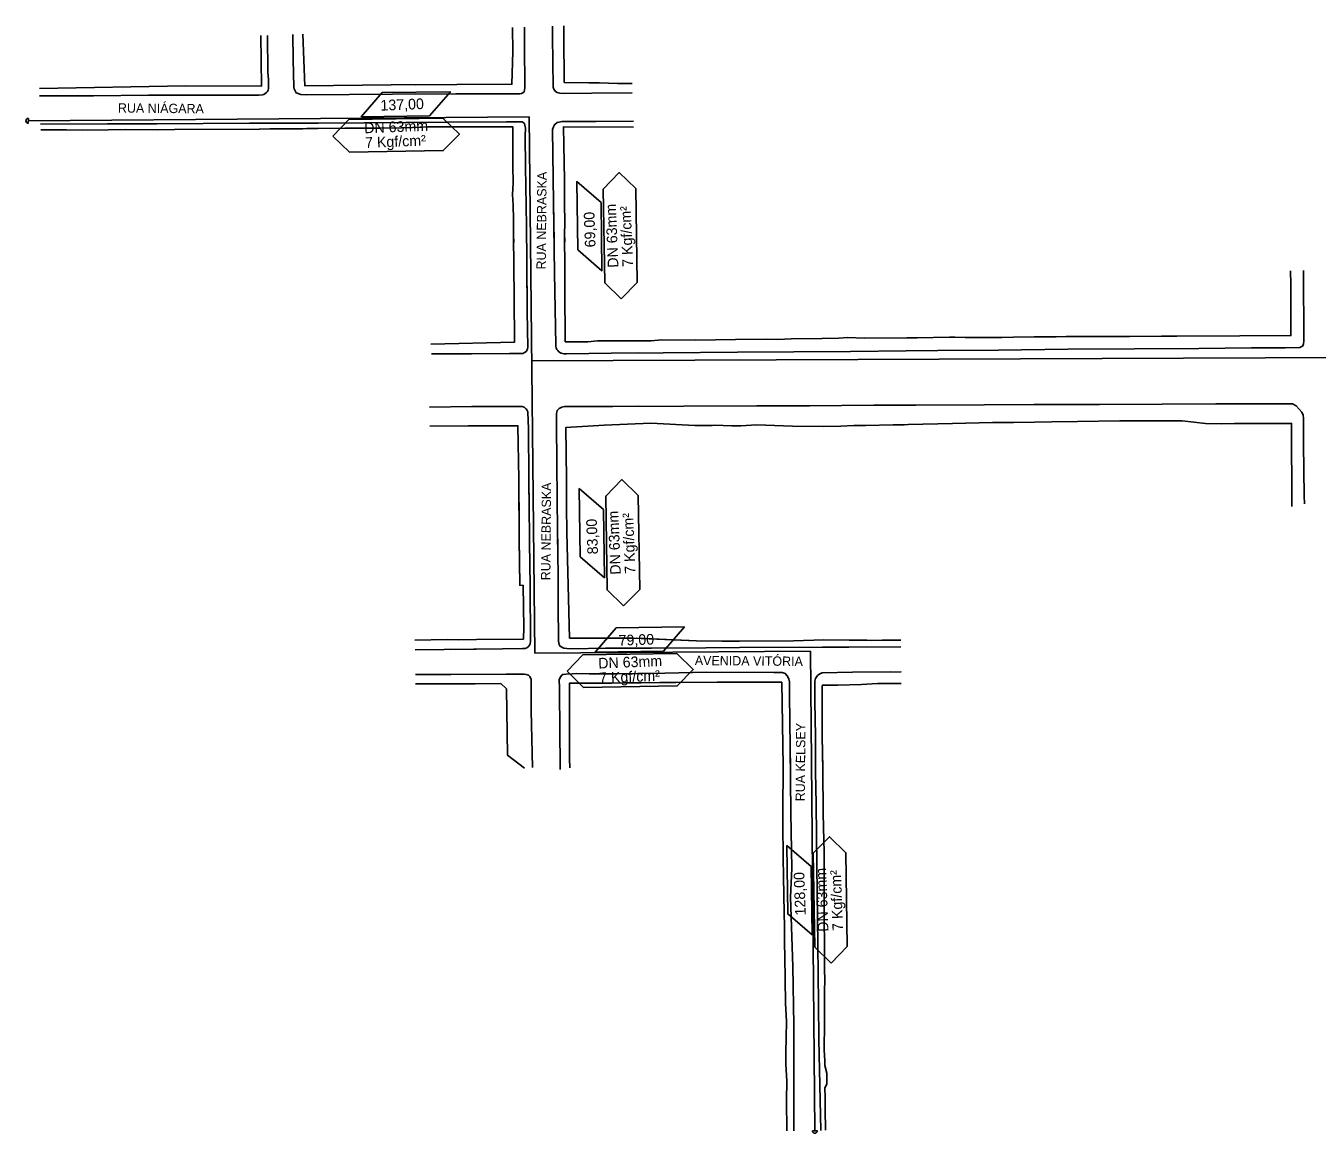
# Model space of a CAD drawing. Extents: x 325899 to 364828, y 7568995 to 7592502.
# Drawn here: x 353880 to 355157, y 7574104 to 7575200 of the extents above; entities that cross this region are included whole.
import ezdxf

# ---------------------------------------------------------------- set-up
doc = ezdxf.new("R2010")
doc.units = 0
for name, color, linetype in [('CERCA_ARAME', 7, 'Continuous'), ('MEIO_FIO_GUIA', 7, 'Continuous'), ('MURO_DIVISA', 7, 'Continuous'), ('SIMBOLO', 7, 'Continuous'), ('TEXTO', 7, 'Continuous'), ('TUBO_PEAD_GN_63', 7, 'Continuous')]:
    doc.layers.add(name, color=color, linetype=linetype)

msp = doc.modelspace()

# ---------------------------------------------------------------- linework, layer by layer
at = {"layer": 'CERCA_ARAME'}
msp.add_line((354480.9, 7574594.1), (354417.9, 7574593.9), dxfattribs=at)
at = {"layer": 'MEIO_FIO_GUIA'}
for points in [[(354144.2, 7575191), (354144.7, 7575166.4), (354145.3, 7575138.9), (354145.6, 7575137.3), (354146.4, 7575136), (354147.6, 7575133.5), (354152.1, 7575131.8), (354157.6, 7575131.5), (354243, 7575131.9), (354305.6, 7575132.2), (354368.8, 7575132.4), (354370.5, 7575132.6), (354371.9, 7575133.3), (354373.1, 7575134.5), (354373.5, 7575136.2), (354373.9, 7575138.2), (354373.5, 7575181.2), (354373.3, 7575198.4)], [(354265.3, 7575132), (354305.6, 7575132.2), (354368.8, 7575132.4), (354370.5, 7575132.6), (354371.9, 7575133.3), (354373.1, 7575134.5), (354373.5, 7575136.2), (354373.9, 7575138.2), (354373.5, 7575181.2), (354373.3, 7575198.4)], [(354401.1, 7575199.3), (354401.2, 7575188.9), (354401.9, 7575139), (354402.4, 7575137), (354404, 7575134.8), (354405.7, 7575133.7), (354408.3, 7575133), (354411.9, 7575132.8), (354440.1, 7575133), (354480.1, 7575133.3)], [(354401.1, 7575199.3), (354401.2, 7575188.9), (354401.9, 7575139), (354402.4, 7575137), (354404, 7575134.8), (354405.7, 7575133.7), (354408.3, 7575133), (354411.9, 7575132.8), (354440.1, 7575133), (354480.1, 7575133.3)], [(353893.9, 7575130.3), (353947.2, 7575130.3), (354001.6, 7575130.9), (354056, 7575131.1), (354102.9, 7575131.2), (354110.7, 7575131.2), (354114.3, 7575131.3), (354115.6, 7575131.8), (354117.1, 7575132.6), (354118.3, 7575133.7), (354119.2, 7575134.8), (354119.8, 7575136.1), (354120.1, 7575137.8), (354120.2, 7575139.2), (354120.1, 7575146.7), (354119.6, 7575153.7), (354119.4, 7575190.2)], [(353894.8, 7575102.4), (353961.1, 7575102.6), (354009.8, 7575102.8), (354101.4, 7575103.3), (354109, 7575103.4), (354169.8, 7575103.5), (354214.9, 7575103.7), (354296.9, 7575104.2), (354355.6, 7575104.6), (354363.5, 7575104.7), (354369.4, 7575104.8), (354371.1, 7575104.6), (354372.3, 7575104.1), (354373.4, 7575103), (354373.9, 7575101.4), (354374.3, 7575098.4), (354374.2, 7575090.7), (354374.6, 7575060.3), (354375.1, 7575022), (354375.3, 7575000.7), (354375.4, 7574985.5)], [(354265.6, 7575104), (354296.9, 7575104.2), (354355.6, 7575104.6), (354363.5, 7575104.7), (354369.4, 7575104.8), (354371.1, 7575104.6), (354372.3, 7575104.1), (354373.4, 7575103), (354373.9, 7575101.4), (354374.3, 7575098.4), (354374.2, 7575090.7), (354374.6, 7575060.3), (354375.1, 7575022), (354375.3, 7575000.7), (354375.6, 7574968.1), (354376.2, 7574916.6), (354376.6, 7574881.9), (354376.4, 7574880.3), (354376, 7574879), (354375.5, 7574878), (354374.2, 7574876.8), (354371.9, 7574875.7), (354369.5, 7574875.4), (354366.7, 7574875.4), (354358.7, 7574875.5), (354321, 7574875.1), (354281.6, 7574875.2)], [(354481.2, 7575105.2), (354444, 7575105), (354417.3, 7575104.9), (354410.4, 7575105), (354407.7, 7575104.4), (354405.8, 7575103.9), (354403.2, 7575101.8), (354402, 7575099.8), (354401.2, 7575097), (354402.1, 7575024.9), (354402.7, 7574985.9)], [(354481.2, 7575105.2), (354444, 7575105), (354417.3, 7575104.9), (354410.4, 7575105), (354407.7, 7575104.4), (354405.8, 7575103.9), (354403.2, 7575101.8), (354402, 7575099.8), (354401.2, 7575097), (354402.1, 7575024.9), (354403.1, 7574955), (354404.3, 7574884), (354404.5, 7574882.4), (354404.8, 7574881.1), (354405.5, 7574879.6), (354406.4, 7574878.5), (354407.3, 7574877.3), (354409, 7574876.3)], [(354375.6, 7574963.4), (354376.2, 7574916.6), (354376.6, 7574881.9), (354376.4, 7574880.3), (354376, 7574879), (354375.5, 7574878), (354374.2, 7574876.8), (354371.9, 7574875.7), (354369.5, 7574875.4), (354366.7, 7574875.4), (354358.7, 7574875.5), (354321, 7574875.1), (354281.6, 7574875.2)], [(354403, 7574963.6), (354403.1, 7574955), (354404.3, 7574884), (354404.5, 7574882.4), (354404.8, 7574881.1), (354405.5, 7574879.6), (354406.4, 7574878.5), (354407.3, 7574877.3), (354409, 7574876.3)], [(354510.5, 7574876.3), (354584, 7574876.8), (354639.7, 7574877.3), (354696, 7574877.6), (354750.9, 7574878.2), (354782.3, 7574878.5), (354842.4, 7574878.9), (354911, 7574879.8), (354976.4, 7574880.1), (355040.3, 7574880.6), (355092.4, 7574881.1), (355117.7, 7574881.3), (355125.7, 7574881.3), (355140.3, 7574881.5), (355142.3, 7574882.4), (355143.2, 7574883.1), (355144, 7574885.1), (355144.3, 7574887.7), (355144, 7574957.7)], [(354409, 7574876.3), (354409.7, 7574875.9), (354412.5, 7574875.3), (354415, 7574875.1), (354459.2, 7574875.8), (354510.5, 7574876.3)], [(354409, 7574876.3), (354409.7, 7574875.9), (354412.5, 7574875.3), (354415, 7574875.1), (354459.2, 7574875.8), (354485.9, 7574876.1)], [(354405.8, 7574720.6), (354405.7, 7574728.3), (354405.4, 7574770.3), (354405, 7574802.3), (354405, 7574810), (354405.1, 7574816.3), (354405.3, 7574817.5), (354405.8, 7574819.3), (354407.6, 7574821.1), (354410.4, 7574822.6), (354413, 7574823), (354460.8, 7574823.2), (354530.8, 7574823.4), (354603.2, 7574823.9), (354655.2, 7574823.9), (354719, 7574824.4), (354760.6, 7574824.3), (354828, 7574824.6), (354877.3, 7574825.1), (354942.3, 7574825.1), (355004.2, 7574825.4), (355057.1, 7574825.6), (355121.5, 7574825.9), (355129.4, 7574825.9), (355133.1, 7574825.8), (355136.6, 7574823.7), (355139.7, 7574820.6), (355142.3, 7574817.5), (355143.6, 7574814.5), (355144, 7574811.4), (355144.1, 7574785.8), (355144.5, 7574734.7), (355144.8, 7574727)], [(354265.4, 7574582.5), (354351.7, 7574583.4), (354371.6, 7574583.9), (354374, 7574583.9), (354375.7, 7574584.4), (354377.5, 7574585.6), (354378.4, 7574587), (354379.1, 7574588.3), (354379.5, 7574591.1), (354379.1, 7574645.9), (354378.3, 7574688.6), (354378.4, 7574693.9), (354377.7, 7574751.8), (354377.3, 7574801.2), (354377.2, 7574808.9), (354376.9, 7574818), (354376.2, 7574819.2), (354375.3, 7574820.4), (354374.4, 7574821.3), (354373, 7574822.5), (354371, 7574823.2), (354365.8, 7574823.1), (354358, 7574823.1), (354321.4, 7574823), (354279.4, 7574822.6)], [(354378.1, 7574720.4), (354377.7, 7574751.8), (354377.3, 7574801.2), (354377.2, 7574808.9), (354376.9, 7574818), (354376.2, 7574819.2), (354375.3, 7574820.4), (354374.4, 7574821.3), (354373, 7574822.5), (354371, 7574823.2), (354365.8, 7574823.1), (354358, 7574823.1), (354321.4, 7574823), (354279.4, 7574822.6)], [(354488.7, 7574584.1), (354453.6, 7574584), (354419.6, 7574583.6), (354415.3, 7574583.7), (354412.2, 7574584.1), (354409.6, 7574585.4), (354408.5, 7574586.4), (354407.7, 7574587.8), (354407.1, 7574590.9), (354406.8, 7574627.7), (354406.6, 7574652.4), (354406.4, 7574680.8), (354405.7, 7574728.3), (354405.4, 7574770.3), (354405, 7574802.3), (354405, 7574810), (354405.1, 7574816.3), (354405.3, 7574817.5), (354405.8, 7574819.3), (354407.6, 7574821.1), (354410.4, 7574822.6), (354413, 7574823), (354460.8, 7574823.2), (354486.4, 7574823.3)], [(354299.8, 7574582.9), (354351.7, 7574583.4), (354371.6, 7574583.9), (354374, 7574583.9), (354375.7, 7574584.4), (354377.5, 7574585.6), (354378.4, 7574587), (354379.1, 7574588.3), (354379.5, 7574591.1), (354379.1, 7574645.9), (354378.3, 7574688.6), (354378.4, 7574691.6)], [(354694.2, 7574585.2), (354668.3, 7574585.1), (354586.1, 7574584.8), (354552.9, 7574584.5), (354499.1, 7574584.1), (354453.6, 7574584), (354419.6, 7574583.6), (354415.3, 7574583.7), (354412.2, 7574584.1), (354409.6, 7574585.4), (354408.5, 7574586.4), (354407.7, 7574587.8), (354407.1, 7574590.9), (354406.8, 7574627.7), (354406.6, 7574652.4), (354406.4, 7574680.8), (354406.2, 7574691.8)], [(354745.7, 7574585.5), (354668.3, 7574585.1), (354586.1, 7574584.8), (354552.9, 7574584.5), (354499.1, 7574584.1), (354484.8, 7574584.1)], [(354265.6, 7574558.1), (354300.6, 7574558.1), (354355.2, 7574558.5), (354373.1, 7574558.4), (354375.2, 7574558.1), (354377.4, 7574557.5), (354378.8, 7574556.1), (354380, 7574553.1), (354379.9, 7574545.1), (354380.2, 7574522.5), (354380.9, 7574480.1), (354381.3, 7574466)], [(354265.6, 7574558.1), (354300.6, 7574558.1), (354355.2, 7574558.5), (354373.1, 7574558.4), (354375.2, 7574558.1), (354377.4, 7574557.5), (354378.8, 7574556.1), (354380, 7574553.1), (354379.9, 7574545.1), (354380.2, 7574522.5), (354380.9, 7574480.1), (354381.3, 7574466)], [(354408.8, 7574464), (354408.3, 7574506.5), (354408, 7574537.8), (354408, 7574545.3), (354407.8, 7574552.9), (354408.6, 7574555.1), (354410, 7574557.2), (354411.4, 7574558), (354414.4, 7574558.4), (354420.7, 7574558.8), (354424.4, 7574558.9), (354437.5, 7574558.8), (354465.3, 7574558.8), (354512.2, 7574559.4), (354553.5, 7574560.3), (354620, 7574559.9), (354628.4, 7574560), (354631.3, 7574559), (354633.4, 7574556.8), (354634.9, 7574553.7), (354635.7, 7574550.8), (354635.6, 7574538.2)], [(354408.8, 7574464), (354408.3, 7574506.5), (354408, 7574537.8), (354408, 7574545.3), (354407.8, 7574552.9), (354408.6, 7574555.1), (354410, 7574557.2), (354411.4, 7574558), (354414.4, 7574558.4), (354420.7, 7574558.8), (354424.4, 7574558.9), (354437.5, 7574558.8), (354465.3, 7574558.8), (354488.9, 7574559.1)], [(354485.4, 7574559), (354512.2, 7574559.4), (354553.5, 7574560.3), (354620, 7574559.9), (354628.4, 7574560), (354631.3, 7574559), (354633.4, 7574556.8), (354634.9, 7574553.7), (354635.7, 7574550.8), (354635.6, 7574538.2)], [(354745.9, 7574560.7), (354745.9, 7574560.7), (354698, 7574560.2), (354668, 7574559.6), (354665.7, 7574558.8), (354663.4, 7574556.9), (354661.4, 7574554.2), (354660.7, 7574551.6), (354660.6, 7574537.8), (354660.6, 7574530.9), (354661.2, 7574497.4), (354661.4, 7574462.2), (354661.9, 7574429.9), (354662.7, 7574368.8), (354663.5, 7574290.6), (354664.1, 7574232.8), (354664.5, 7574197.2), (354666.7, 7574107.1)], [(354735.7, 7574560.6), (354735.7, 7574560.6), (354698, 7574560.2), (354668, 7574559.6), (354665.7, 7574558.8), (354663.4, 7574556.9), (354661.4, 7574554.2), (354660.7, 7574551.6), (354660.6, 7574537.8), (354660.6, 7574530.9), (354661.2, 7574497.4), (354661.4, 7574465.1)], [(354635.6, 7574538.1), (354636.2, 7574486.3), (354636.4, 7574465)], [(354635.6, 7574538.1), (354636.2, 7574486.3), (354636.9, 7574421.1), (354637.9, 7574366.1), (354636.6, 7574337.9), (354638.8, 7574269.3), (354639.8, 7574211.1), (354639.8, 7574121.2), (354640, 7574106.8)]]:
    msp.add_lwpolyline(points, dxfattribs=at)
at = {"layer": 'MURO_DIVISA'}
for p, q in [((354452.3, 7574804.8), (354498.5, 7574806.5)), ((354480.9, 7574594.1), (354417.9, 7574593.9))]:
    msp.add_line(p, q, dxfattribs=at)
for points in [[(354154.2, 7575191.3), (354156.1, 7575140.4), (354241.5, 7575141.3), (354306.5, 7575141.6), (354361, 7575141.8), (354361.8, 7575174.1), (354361.6, 7575198)], [(354265.2, 7575141.4), (354306.5, 7575141.6), (354361, 7575141.8), (354361.8, 7575174.1), (354361.6, 7575198)], [(354412.2, 7575199.6), (354412.3, 7575190.1), (354412.8, 7575143.6), (354437, 7575143.2), (354447.7, 7575143.3), (354465.6, 7575142.7), (354477.4, 7575142.7)], [(354412.2, 7575199.6), (354412.3, 7575190.1), (354412.8, 7575143.6), (354437, 7575143.2), (354447.7, 7575143.3), (354465.6, 7575142.7), (354479.8, 7575142.7)], [(353893.7, 7575137.6), (354038.6, 7575140.3), (354113.2, 7575139.8), (354112.8, 7575190)], [(353895, 7575096.7), (353920.6, 7575096.6), (353936, 7575096.5), (353962, 7575096.8), (353978.9, 7575097), (354010.6, 7575096.9), (354027.2, 7575097.1), (354111.1, 7575097.3), (354111.1, 7575097.3), (354111.1, 7575097.3)], [(354111.1, 7575097.3), (354111.1, 7575097.3), (354121.7, 7575097.6), (354154.2, 7575097.8), (354158.2, 7575098), (354169.2, 7575098.1), (354195.7, 7575098.3), (354219.8, 7575098.5), (354231.1, 7575098.5), (354251.8, 7575098.8), (354262.8, 7575099.1), (354277.4, 7575099.6), (354287.9, 7575099.8), (354362, 7575099.6), (354361.9, 7575069.3), (354361.9, 7575061.1), (354362.1, 7575044), (354361.7, 7575032.9), (354362.3, 7575022.3), (354362.4, 7575017.8), (354362.6, 7575012.5), (354362.7, 7575002.8), (354362.7, 7574992.1), (354362.8, 7574985.4)], [(354265.6, 7575099.2), (354277.4, 7575099.6), (354287.9, 7575099.8), (354362, 7575099.6), (354361.9, 7575069.3), (354361.9, 7575061.1), (354362.1, 7575044), (354361.7, 7575032.9), (354362.3, 7575022.3), (354362.4, 7575017.8), (354362.6, 7575012.5), (354362.7, 7575002.8), (354362.7, 7574992.1), (354363.2, 7574931.1), (354363.2, 7574931.1)], [(354481.2, 7575099.3), (354412, 7575099.6), (354412.4, 7575082), (354412.9, 7575047), (354413.1, 7575036.3), (354413, 7575020.5), (354413.2, 7575008.4), (354413.2, 7575003.6), (354413.1, 7574994.6), (354413.2, 7574986)], [(354481.2, 7575099.3), (354412, 7575099.6), (354412.4, 7575082), (354412.9, 7575047), (354413.1, 7575036.3), (354413, 7575020.5), (354413.2, 7575008.4), (354413.2, 7575003.6), (354413.1, 7574994.6), (354413.3, 7574957.8), (354413.5, 7574944.3), (354413.5, 7574939.6), (354413.7, 7574887.2), (354436.1, 7574887), (354445.5, 7574887.9), (354485.8, 7574888.1)], [(354413.3, 7574963.6), (354413.3, 7574957.8), (354413.5, 7574944.3), (354413.5, 7574939.6), (354413.7, 7574887.2), (354436.1, 7574887), (354445.5, 7574887.9), (354498.9, 7574888.2), (354508.8, 7574888.9), (354542.6, 7574888.8), (354582.1, 7574889.5), (354612.9, 7574889.7), (354624, 7574889.5), (354637.3, 7574889.9), (354667.7, 7574890.4), (354684.2, 7574890.7), (354693.4, 7574891.5), (354709.5, 7574890.8), (354751.6, 7574891), (354761.9, 7574891.1), (354793.7, 7574891.7), (354799, 7574891.7), (354809.4, 7574891.4), (354821.9, 7574891.4), (354832.4, 7574891.3), (354835.2, 7574891.4), (354845.5, 7574891.5), (354857.2, 7574891.8), (354877.5, 7574892), (354899.3, 7574892.1), (354909.3, 7574892.3), (354920.1, 7574892.4), (354930.4, 7574892.2), (354962.1, 7574892.2), (354971.8, 7574892.2), (355003.5, 7574892.7), (355018.8, 7574892.6), (355080.9, 7574893), (355131.5, 7574893.3), (355131.6, 7574943.7), (355131.2, 7574957.3)], [(354280.7, 7574884.8), (354363.7, 7574886.9), (354363.2, 7574931.1)], [(354265.1, 7574591.9), (354296.8, 7574592.6), (354308.1, 7574592.4), (354325.9, 7574592.6), (354372.4, 7574592.9), (354372.6, 7574593.2), (354372.7, 7574604.3), (354372.3, 7574646.1), (354368.8, 7574646.4), (354368.2, 7574693), (354368.2, 7574705.9), (354367.7, 7574751.2), (354367, 7574804), (354317.6, 7574803.9), (354279.7, 7574803.6)], [(354368, 7574720.4), (354367.7, 7574751.2), (354367, 7574804), (354317.6, 7574803.9), (354279.7, 7574803.6)], [(354415, 7574720.6), (354414.9, 7574724.3), (354414.9, 7574747.9), (354415, 7574751.1), (354414.5, 7574802.4), (354452.3, 7574804.8), (354414.5, 7574802.4)], [(354417.9, 7574593.9), (354415.3, 7574698.5), (354414.9, 7574724.3), (354414.9, 7574747.9), (354415, 7574751.1), (354414.5, 7574802.4), (354452.3, 7574804.8), (354414.5, 7574802.4)], [(354498.5, 7574806.5), (354541.9, 7574804.3), (354546.8, 7574804.2), (354559.1, 7574804.4), (354561.5, 7574804.6), (354578.4, 7574804), (354587.4, 7574804), (354603.3, 7574804.9), (354629.6, 7574803.9), (354638.5, 7574803.8), (354669, 7574803.3), (354686.4, 7574803.6), (354699.2, 7574804.3), (354710.8, 7574804.4), (354738.1, 7574804.9), (354749.1, 7574805.1), (354752.9, 7574805.3), (354796.8, 7574806.2), (354836.4, 7574807.2), (354857.2, 7574807.3), (354877.8, 7574807.6), (354894.6, 7574807.8), (354920.4, 7574808.3), (354962.4, 7574808.9), (354985.3, 7574808.9), (354999.6, 7574809), (355004.5, 7574809), (355010.1, 7574809.1), (355024, 7574809.1), (355047, 7574806.4), (355063.2, 7574806.1), (355075.8, 7574806.2), (355132.1, 7574806.4), (355132.5, 7574724.3)], [(354283.8, 7574592.3), (354296.8, 7574592.6), (354308.1, 7574592.4), (354325.9, 7574592.6), (354372.4, 7574592.9), (354372.6, 7574593.2), (354372.7, 7574604.3), (354372.3, 7574646.1), (354368.8, 7574646.4), (354368.3, 7574691.6)], [(354727.3, 7574592.1), (354716.7, 7574591.8), (354711.9, 7574592), (354705, 7574592.1), (354694.7, 7574592.1), (354669.4, 7574592.4), (354639.5, 7574591.3), (354586.2, 7574591.1), (354579.8, 7574591.1), (354568.5, 7574591), (354543.7, 7574591.2), (354480.9, 7574594.1), (354480.9, 7574594.1)], [(354745.6, 7574592.1), (354727.3, 7574592.1), (354716.7, 7574591.8), (354711.9, 7574592), (354705, 7574592.1), (354694.7, 7574592.1), (354669.4, 7574592.4), (354639.5, 7574591.3), (354586.2, 7574591.1), (354579.8, 7574591.1), (354568.5, 7574591), (354543.7, 7574591.2), (354484.5, 7574594)], [(354373.3, 7574465.3), (354356.8, 7574478.2), (354355.6, 7574543.8), (354350.2, 7574549.1), (354324.7, 7574548.8), (354278.3, 7574548.9), (354267.2, 7574548.8), (354265.7, 7574548.7)], [(354373.3, 7574465.3), (354356.8, 7574478.2), (354355.6, 7574543.8), (354350.2, 7574549.1), (354324.7, 7574548.8), (354278.3, 7574548.9), (354267.2, 7574548.8), (354265.7, 7574548.7)], [(354627.9, 7574550.6), (354605.4, 7574550.5), (354564, 7574550.4), (354523, 7574550.1), (354507.4, 7574550), (354497.4, 7574549.9), (354496, 7574550), (354486.1, 7574549.8), (354470.6, 7574549.8), (354459.9, 7574549.5), (354451.2, 7574549.5), (354417.9, 7574549.4), (354417.8, 7574521.8), (354418.1, 7574474.7), (354418.3, 7574465.8)], [(354489, 7574549.9), (354486.1, 7574549.8), (354470.6, 7574549.8), (354459.9, 7574549.5), (354451.2, 7574549.5), (354417.9, 7574549.4), (354417.8, 7574521.8), (354418.1, 7574474.7), (354418.3, 7574465.8)], [(354627.9, 7574550.6), (354605.4, 7574550.5), (354564, 7574550.4), (354523, 7574550.1), (354507.4, 7574550), (354497.4, 7574549.9), (354496, 7574550), (354486.1, 7574549.8), (354485.6, 7574549.8)], [(354632.8, 7574106.6), (354632.7, 7574136.9), (354632.8, 7574155.8), (354632, 7574172.6), (354632.1, 7574184.5), (354632.3, 7574198.6), (354632.5, 7574215.2), (354631.6, 7574232.5), (354631.3, 7574256.8), (354630.9, 7574278.8), (354630.7, 7574292.3), (354630.6, 7574297.2), (354630.5, 7574307.8), (354630.1, 7574338.9), (354630.1, 7574344.5), (354629.7, 7574353.9), (354629.3, 7574380.9), (354629.3, 7574390.7), (354629.1, 7574396.4), (354629, 7574409.5), (354629.1, 7574418.1), (354628.9, 7574422.3), (354629.2, 7574467.5), (354627.9, 7574550.5)], [(354667.9, 7574547.3), (354667.8, 7574507.5), (354667.9, 7574497), (354668.4, 7574465.1)], [(354667.9, 7574547.3), (354667.8, 7574507.5), (354667.9, 7574497), (354668.4, 7574463), (354668.9, 7574422), (354669.3, 7574405.6), (354669.5, 7574395.5), (354669.7, 7574381.3), (354670, 7574339), (354670.2, 7574267.2), (354670.4, 7574255), (354670.2, 7574245.7), (354670.2, 7574234.7), (354670.3, 7574222.3), (354670.2, 7574213.2), (354670, 7574186.7), (354670.6, 7574175.9), (354670.6, 7574171.2), (354672.5, 7574163.6), (354672.5, 7574152.8), (354670.6, 7574149.1), (354670.8, 7574139.3), (354670.9, 7574128), (354671.3, 7574107.4)], [(354746, 7574549.1), (354731.2, 7574549), (354722.7, 7574549.1), (354706.8, 7574548.3), (354683.3, 7574547.6), (354667.9, 7574547.4)], [(354746, 7574549.1), (354731.2, 7574549), (354722.7, 7574549.1), (354706.8, 7574548.3), (354683.3, 7574547.6), (354667.9, 7574547.4)]]:
    msp.add_lwpolyline(points, dxfattribs=at)
at = {"layer": 'SIMBOLO'}
for points in [[(354279.4, 7575110.5), (354211.9, 7575109.6), (354232.6, 7575133.6), (354300.1, 7575134.5)], [(354449.2, 7575024.8), (354450.1, 7574957.3), (354426.1, 7574978.1), (354425.2, 7575045.6)], [(354451.6, 7574721.2), (354452.5, 7574653.7), (354428.5, 7574674.5), (354427.6, 7574742)], [(354510.8, 7574581.1), (354443.4, 7574580.2), (354464.1, 7574604.2), (354531.6, 7574605.1)], [(354657, 7574368.1), (354657.9, 7574300.6), (354633.9, 7574321.3), (354633, 7574388.8)]]:
    msp.add_lwpolyline(points, close=True, dxfattribs=at)
for points in [[(354184, 7575090.6), (354199.8, 7575106.9), (354292.6, 7575108.4), (354309, 7575092.5), (354293.1, 7575076.2), (354200.4, 7575074.8), (354184, 7575090.6)], [(354469.1, 7574929.5), (354452.8, 7574945.3), (354451.3, 7575038.1), (354467.2, 7575054.4), (354483.5, 7575038.6), (354484.9, 7574945.8), (354469.1, 7574929.5)], [(354471.5, 7574625.9), (354455.2, 7574641.7), (354453.8, 7574734.5), (354469.6, 7574750.8), (354485.9, 7574735), (354487.4, 7574642.2), (354471.5, 7574625.9)], [(354415.5, 7574561.2), (354431.3, 7574577.5), (354524.1, 7574578.9), (354540.4, 7574563.1), (354524.6, 7574546.8), (354431.8, 7574545.3), (354415.5, 7574561.2)], [(354676.9, 7574272.7), (354660.6, 7574288.5), (354659.1, 7574381.3), (354675, 7574397.6), (354691.3, 7574381.8), (354692.7, 7574289.1), (354676.9, 7574272.7)]]:
    msp.add_lwpolyline(points, dxfattribs=at)
at = {"layer": 'TUBO_PEAD_GN_63'}
for p, q in [((353882.6, 7575103.2), (353882.7, 7575108.1)), ((353882.7, 7575105.6), (354378, 7575109.6)), ((354378, 7575109.6), (354383.7, 7574579)), ((356604.1, 7574877.9), (354380.6, 7574868.2)), ((354656.5, 7574581.2), (354383.7, 7574579)), ((354656.5, 7574581.2), (354660.6, 7574106.8)), ((354663.1, 7574106.8), (354658.2, 7574106.8))]:
    msp.add_line(p, q, dxfattribs=at)
for centre, start, end in [((353882.7, 7575105.6), 89.8591, 269.8591), ((354660.6, 7574106.8), 179.8591, 359.8591)]:
    msp.add_arc(centre, 2.44, start, end, dxfattribs=at)

# ---------------------------------------------------------------- texts
at = {"layer": 'TEXTO'}
for s, height, rotation, p in [('RUA NIÁGARA', 9.221, 359.5098, (353971.3, 7575113.8)), ('137,00', 10.5, 2.2907, (354231.2, 7575115.7)), ('DN 63mm', 10.5, 2.2907, (354215.1, 7575093.3)), ('7 Kgf/cm²', 10.5, 2.2907, (354216, 7575078.8)), ('RUA NEBRASKA', 9.221, 89.5098, (354394.5, 7574958.6)), ('DN 63mm', 10.5, 92.2907, (354466.4, 7574960.6)), ('7 Kgf/cm²', 10.5, 92.2907, (354480.9, 7574961.5)), ('69,00', 10.5, 92.0817, (354443.8, 7574980.7)), ('RUA NEBRASKA', 9.221, 89.5098, (354399, 7574651.2)), ('83,00', 10.5, 92.0817, (354446.2, 7574677.1)), ('DN 63mm', 10.5, 92.2907, (354468.8, 7574657)), ('7 Kgf/cm²', 10.5, 92.2907, (354483.3, 7574657.9)), ('79,00', 10.5, 2.0817, (354466.7, 7574586.5)), ('DN 63mm', 10.5, 2.2907, (354446.6, 7574563.9)), ('AVENIDA VITÓRIA', 9.221, 359.5098, (354541.9, 7574567.4)), ('7 Kgf/cm²', 10.5, 2.2907, (354447.5, 7574549.4)), ('RUA KELSEY', 9.22, 89.5098, (354650.7, 7574432.6)), ('DN 63mm', 10.5, 92.2907, (354674.2, 7574303.8)), ('128,00', 10.5, 92.0817, (354651.7, 7574319.9)), ('7 Kgf/cm²', 10.5, 92.2907, (354688.7, 7574304.7))]:
    msp.add_text(s, height=height, rotation=rotation, dxfattribs=at).set_placement(p)

doc.saveas('drawing.dxf')
